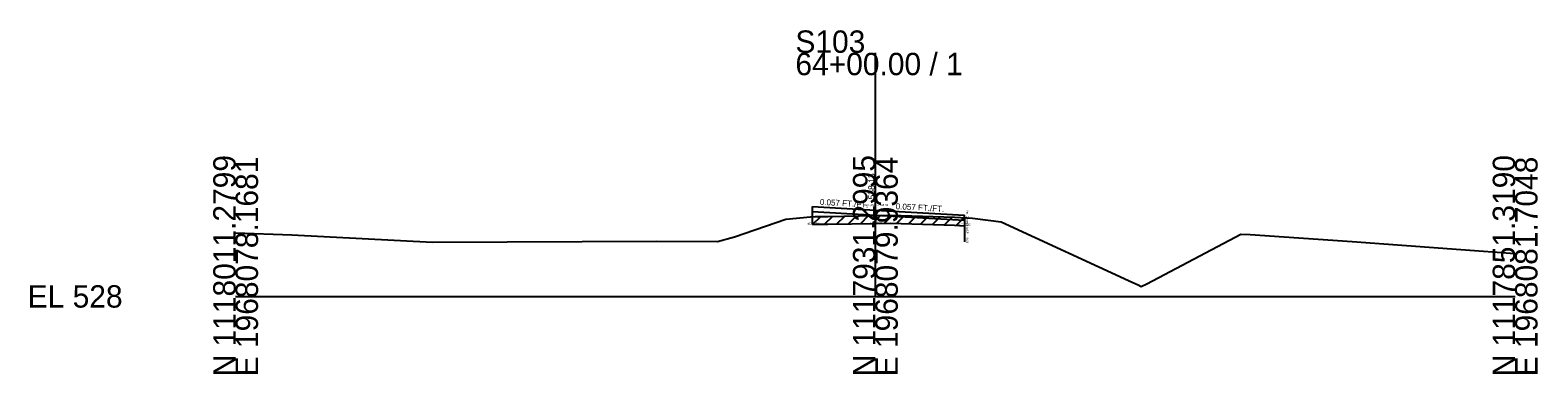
# Model space of a CAD drawing. Extents: x -26 to 163, y -10 to 24018.
# Drawn here: x -25.7 to 162.8, y 11990.3 to 12033.3 of the extents above; entities that cross this region are included whole.
import ezdxf

# ---------------------------------------------------------------- set-up
doc = ezdxf.new("R2010")
doc.units = 0
for name, color, linetype in [('RD_GPK_XS_Cell', 7, 'Continuous'), ('RD_XS_ExGround', 7, 'Continuous'), ('RD_XS_ExPaveRet', 7, 'Continuous'), ('RD_XS_Misc_Line', 7, 'Continuous'), ('RD_XS_PaveOvlay_CP', 7, 'Continuous'), ('RD_XS_TX_Elev_EX', 7, 'Continuous'), ('RD_XS_TX_ExEOP', 7, 'Continuous'), ('RD_XS_TX_Notes', 7, 'Continuous'), ('RD_XS_TX_Profile', 7, 'Continuous'), ('RD_XS_TX_Slope', 7, 'Continuous')]:
    doc.layers.add(name, color=color, linetype=linetype)

msp = doc.modelspace()

# ---------------------------------------------------------------- linework, layer by layer
at = {"layer": 'RD_GPK_XS_Cell'}
for p, q in [((80, 12000), (80, 12030.48)), ((0, 12000), (80, 12000)), ((80, 12000), (160, 12000))]:
    msp.add_line(p, q, dxfattribs=at)
at = {"layer": 'RD_XS_ExGround'}
msp.add_lwpolyline([(0, 12007.94), (7.01, 12007.72), (24.6, 12006.78), (52.68, 12006.92), (60.25, 12006.88), (62.37, 12007.47), (68.81, 12009.65), (71.88, 12009.95), (72.48, 12010.02), (74.04, 12010.02), (80, 12010.13), (81.89, 12010.16), (89.91, 12009.91), (91.44, 12009.84), (92.15, 12009.77), (95.74, 12009.32), (112.19, 12001.73), (112.87, 12001.46), (113.22, 12001.24), (113.95, 12001.59), (125.7, 12007.77), (126.86, 12007.74), (139.64, 12006.87), (160, 12005.35)], dxfattribs=at)
at = {"layer": 'RD_XS_ExPaveRet'}
for p, q in [((72.15, 12008.98), (73.19, 12010.02)), ((72.15, 12008.98), (72.15, 12009.98)), ((73.65, 12009.02), (74.66, 12010.03)), ((75.15, 12009.04), (76.16, 12010.06)), ((76.65, 12009.07), (77.66, 12010.09)), ((78.15, 12009.09), (79.16, 12010.11)), ((79.65, 12009.12), (80.66, 12010.14)), ((81.15, 12009.15), (82.15, 12010.15)), ((82.65, 12009.14), (83.61, 12010.1)), ((84.15, 12009.09), (85.11, 12010.06)), ((85.65, 12009.04), (86.61, 12010.01)), ((87.15, 12008.99), (88.11, 12009.96)), ((88.65, 12008.95), (89.61, 12009.92)), ((90.15, 12008.9), (91.11, 12009.86)), ((91.13, 12009.85), (91.13, 12008.85)), ((72.15, 12008.98), (72.48, 12009.02)), ((72.48, 12009.02), (74.04, 12009.02)), ((74.04, 12009.02), (80, 12009.13)), ((80, 12009.13), (81.89, 12009.16)), ((81.89, 12009.16), (89.91, 12008.91)), ((89.91, 12008.91), (91.13, 12008.85))]:
    msp.add_line(p, q, dxfattribs=at)
at = {"layer": 'RD_XS_Misc_Line'}
msp.add_line((91.13, 12009.85), (91.13, 12006.85), dxfattribs=at)
at = {"layer": 'RD_XS_PaveOvlay_CP'}
for p, q in [((72.15, 12011.26), (80, 12010.81)), ((72.15, 12009.98), (72.15, 12011.26)), ((80, 12010.13), (72.15, 12010.57)), ((80, 12010.81), (91.13, 12010.17)), ((91.13, 12009.49), (80, 12010.13)), ((91.13, 12009.85), (91.13, 12010.17))]:
    msp.add_line(p, q, dxfattribs=at)

# ---------------------------------------------------------------- texts
at = {"layer": 'RD_GPK_XS_Cell'}
for s, p in [('S103', (70, 12030.48)), ('64+00.00 / 1', (70, 12027.68)), ('EL 528', (-26, 11998.6))]:
    msp.add_text(s, height=2.8, dxfattribs=at).set_placement(p)
for s, p in [('N 1118011.2799', (0, 11990)), ('E 1968078.1681', (2.8, 11990)), ('N 1117931.2995', (80, 11990)), ('E 1968079.9364', (82.8, 11990)), ('N 1117851.3190', (160, 11990)), ('E 1968081.7048', (162.8, 11990))]:
    msp.add_text(s, height=2.8, rotation=90, dxfattribs=at).set_placement(p)
at = {"layer": 'RD_XS_TX_Elev_EX'}
msp.add_text('538.13', height=0.8, rotation=90, dxfattribs=at).set_placement((79.9, 12012.13))
at = {"layer": 'RD_XS_TX_ExEOP'}
for s, p in [('EOP-L', (72.1, 12011.26)), ('EOP-R', (91.08, 12010.17))]:
    msp.add_text(s, height=0.1, rotation=270, dxfattribs=at).set_placement(p)
at = {"layer": 'RD_XS_TX_Notes'}
for s, p in [('Elev. @CL = 538.81', (78.49, 12011.31)), (' dE= 1.28', (71.43, 12008.98)), (' dE= 0.68', (79.29, 12009.13)), (' dE= 0.32', (90.42, 12008.85))]:
    msp.add_text(s, height=0.25, dxfattribs=at).set_placement(p)
msp.add_text(' Min. Distance @CP = -0.36', height=0.25, rotation=270, dxfattribs=at).set_placement((91.38, 12010.95))
at = {"layer": 'RD_XS_TX_Profile'}
msp.add_text('CL', height=0.25, dxfattribs=at).set_placement((79.77, 12010.81))
at = {"layer": 'RD_XS_TX_Slope'}
for p in [(73.04, 12011.46), (82.53, 12010.92)]:
    msp.add_text('0.057 FT./FT.', height=0.75, rotation=356.7359, dxfattribs=at).set_placement(p)

doc.saveas('drawing.dxf')
